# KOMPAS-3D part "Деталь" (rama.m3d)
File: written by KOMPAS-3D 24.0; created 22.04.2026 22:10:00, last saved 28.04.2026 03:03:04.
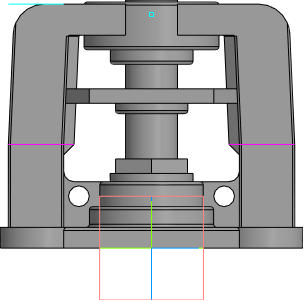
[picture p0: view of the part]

Document properties: Автор: mrdid; Полное имя файла: C:\Работа\ГОТОВЫЕ ИСХОДНИКИ\VSO2130M-F-S Клапан запорный сильфонный DN.ru Ду15-100 Ру40\исходные материалы\DN80\rama.m3d

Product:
- Part/product: Деталь
    Масса: 5.908059

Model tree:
1. Эскиз:2  (with: Ребро.Элемент выдавливания:14)
2. Элемент выдавливания:1
     Расстояние 1 = 10
3. Эскиз:3  (with: Грань.Элемент выдавливания:1, Ребро.Элемент выдавливания:1)
4. Элемент выдавливания:2
     Расстояние 2 = 10
5. Эскиз:4  (with: Грань.Элемент выдавливания:1)
6. Элемент выдавливания:3
     Расстояние 1 = 10
7. Эскиз:5  (with: Грань.Элемент выдавливания:3, Ребро.Элемент выдавливания:3)
8. Элемент выдавливания:4
     Расстояние 1 = 12
9. Эскиз:6  (with: Грань.Элемент выдавливания:1, Ребро.Элемент выдавливания:1)
10. Элемент выдавливания:5
     Расстояние 1 = 40
11. Эскиз:23  (with: Грань.Элемент выдавливания:4, Ребро.Элемент выдавливания:4)
12. Элемент выдавливания:21
     Расстояние 1 = 11
13. Эскиз:7  (with: Грань.Элемент выдавливания:21, Ребро.Элемент выдавливания:3)
14. Элемент выдавливания:6
     Расстояние 2 = 7
15. Эскиз:8  (with: Грань.Элемент выдавливания:5, Ребро.Элемент выдавливания:5)
16. Смещенная плоскость:1  (with: Грань.Элемент выдавливания:5)
17. Эскиз:9
18. Элемент по сечениям:1
19. Элемент по сечениям:2
20. Эскиз:10
21. Элемент выдавливания:8
     Расстояние 2 = 15
22. Эскиз:11  (with: Грань.Элемент выдавливания:8, Ребро.Элемент выдавливания:3)
23. Элемент выдавливания:9  (with: Грань.Элемент выдавливания:8)
     Расстояние 1 = 1; Расстояние 2 = 22; Смещение 2 = 7
24. Эскиз:12  (with: Грань.Элемент выдавливания:9, Ребро.Элемент выдавливания:9)
25. Элемент выдавливания:10
     Расстояние 1 = 7
26. Эскиз:13  (with: Грань.Элемент выдавливания:21, Ребро.Элемент выдавливания:3)
27. Элемент выдавливания:11  (with: Грань.Элемент выдавливания:10)
     Расстояние 1 = 45.64
28. Смещенная плоскость:2  (with: Грань.Элемент выдавливания:21)
29. Эскиз:14  (with: Ребро.Элемент по сечениям:2, Ребро.Элемент по сечениям:1)
30. Элемент выдавливания:12
     Расстояние 1 = 7
31. Эскиз:15  (with: Грань.Элемент выдавливания:12, Ребро.Элемент выдавливания:3)
32. Элемент выдавливания:13
     Расстояние 1 = 5
33. Эскиз:16  (with: Ребро.Элемент выдавливания:5, Ребро.Элемент выдавливания:1, Ребро.Элемент выдавливания:4)
34. Элемент выдавливания:14
     Расстояние 1 = 4
35. Элемент выдавливания:15
     Расстояние 1 = 2
36. Эскиз:17  (with: Ребро.Элемент выдавливания:14, Ребро.Элемент выдавливания:5)
37. Элемент выдавливания:16
     Расстояние 1 = 73; Расстояние 2 = 73
38. Скругление:1  (with: Ребро.Элемент выдавливания:1, Ребро.Элемент выдавливания:3)
     Радиус = 1.5
39. Скругление:2  (with: Ребро.Элемент выдавливания:9, Ребро.Элемент выдавливания:10, Ребро.Элемент выдавливания:4, Ребро.Элемент выдавливания:13)
40. Эскиз:18  (with: Грань.Элемент выдавливания:9)
41. Элемент выдавливания:17
     Расстояние 1 = 1
42. Скругление:3  (with: Ребро.Элемент по сечениям:2, Ребро.Элемент по сечениям:1)
     Радиус = 15
43. Скругление:4  (with: Ребро.Элемент выдавливания:8)
     Радиус = 0.5
44. Скругление:5  (with: Ребро.Элемент выдавливания:14)
     Радиус = 5
45. Эскиз:19  (with: Ребро.Элемент выдавливания:17)
46. Элемент выдавливания:18  (with: Грань.Элемент выдавливания:9)
     Смещение 1 = 5
47. Смещенная плоскость:3  (with: Грань.Элемент выдавливания:18)
     Расстояние = 2
48. Эскиз:20  (with: Ребро.Элемент выдавливания:18)
49. Элемент выдавливания:19
     Расстояние 2 = 0.2
50. Скругление:6  (with: Ребро.Элемент выдавливания:18)
     Радиус = 1
51. Эскиз:21  (with: Ребро.Элемент выдавливания:19)
52. Элемент выдавливания:20
     Расстояние 1 = 10
53. Скругление:7  (with: Ребро.Элемент по сечениям:2, Ребро.Элемент выдавливания:5, Ребро.Элемент по сечениям:1)
     Радиус = 1
54. Фаска:1  (with: Ребро.Элемент по сечениям:1, Ребро.Элемент по сечениям:2)
     Угол = 45; Длина 1 = 5; Длина 2 = 5
55. Массив по концентрической сетке:1  (with: Элемент выдавливания:2, Эскиз:3)  (labels: Клапан запорный DN.ru Ду80 Ру40)  (4 pattern instances)
     Шаг 2 = 360

Expressions: DN/2; v249/2; DN/3
Referenced files in C:\Работа\ГОТОВЫЕ ИСХОДНИКИ\VSO2130M-F-S Клапан запорный сильфонный DN.ru Ду15-100 Ру40\исходные материалы\DN80\: VSO2130M-F-S Клапан запорный DN.ru Ду80 Ру40.a3d
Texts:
  DN+5
  DN-20
  DN-15
  Ось Y.Начало координат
